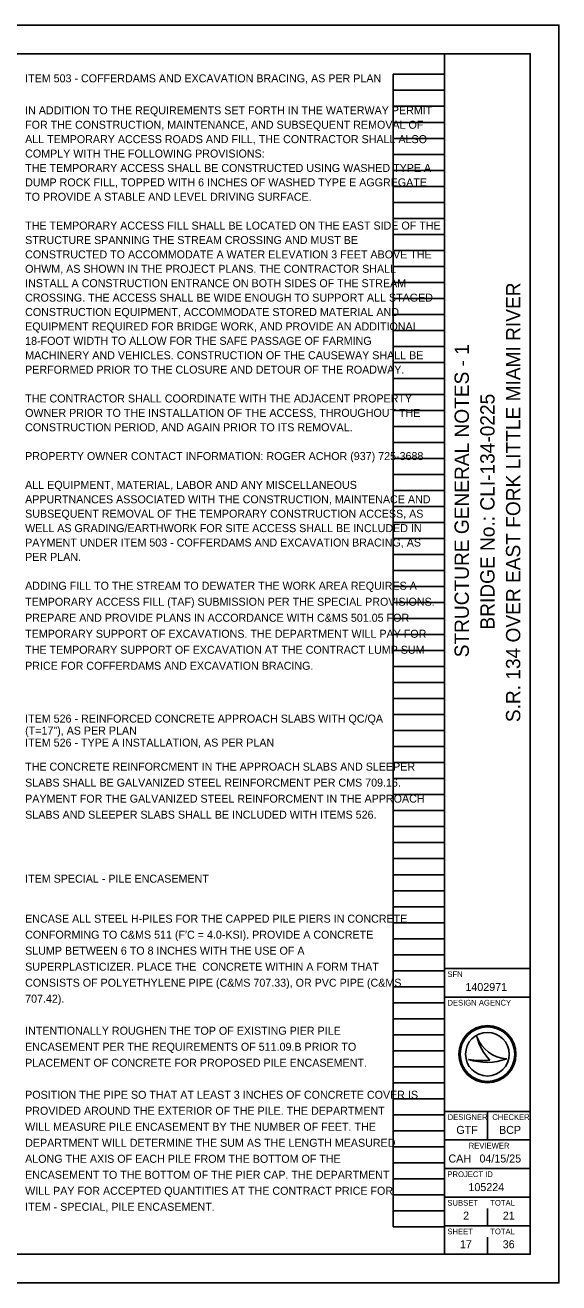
# Model space of a CAD drawing. Extents: x 0 to 48.4, y -19.4 to 22.
# Drawn here: x 24.66 to 34, y 0 to 22 of the extents above; entities that cross this region are included whole.
import ezdxf

# ---------------------------------------------------------------- set-up
doc = ezdxf.new("R2010")
doc.units = 0
for name, color, linetype in [('BR_P_Gen_Text', 7, 'Continuous'), ('SH_Border', 7, 'Continuous'), ('SH_Cut_Line', 7, 'Continuous'), ('SH_Data', 7, 'Continuous'), ('SH_Text', 7, 'Continuous')]:
    doc.layers.add(name, color=color, linetype=linetype)

msp = doc.modelspace()

# ---------------------------------------------------------------- linework, layer by layer
at = {"layer": 'SH_Border'}
for p, q in [((32, 0.5), (32, 21.5)), ((32, 5.5), (33.5, 5.5)), ((32, 5), (33.5, 5)), ((32, 3), (33.5, 3)), ((32.75, 3), (32.75, 2.5)), ((32, 2.5), (33.5, 2.5)), ((32, 2), (33.5, 2)), ((32, 1.5), (33.5, 1.5)), ((32, 1), (33.5, 1))]:
    msp.add_line(p, q, dxfattribs=at)
msp.add_lwpolyline([(1.5, 21.5), (33.5, 21.5), (33.5, 0.5), (1.5, 0.5)], close=True, dxfattribs=at)
at = {"layer": 'SH_Cut_Line'}
msp.add_lwpolyline([(0, 0), (34, 0), (34, 22), (0, 22)], close=True, dxfattribs=at)
at = {"layer": 'SH_Data'}
for p, q in [((31.1, 0.98), (31.1, 21.14)), ((31.1, 21.14), (32, 21.14)), ((32, 0.98), (32, 21.14)), ((31.1, 20.86), (32, 20.86)), ((31.1, 20.58), (32, 20.58)), ((31.1, 20.3), (32, 20.3)), ((31.1, 20.02), (32, 20.02)), ((31.1, 19.74), (32, 19.74)), ((31.1, 19.46), (32, 19.46)), ((31.1, 19.18), (32, 19.18)), ((31.1, 18.9), (32, 18.9)), ((31.1, 18.62), (32, 18.62)), ((31.1, 18.34), (32, 18.34)), ((31.1, 18.06), (32, 18.06)), ((31.1, 17.78), (32, 17.78)), ((31.1, 17.5), (32, 17.5)), ((31.1, 17.22), (32, 17.22)), ((31.1, 16.94), (32, 16.94)), ((31.1, 16.66), (32, 16.66)), ((31.1, 16.38), (32, 16.38)), ((31.1, 16.1), (32, 16.1)), ((31.1, 15.82), (32, 15.82)), ((31.1, 15.54), (32, 15.54)), ((31.1, 15.26), (32, 15.26)), ((31.1, 14.98), (32, 14.98)), ((31.1, 14.7), (32, 14.7)), ((31.1, 14.42), (32, 14.42)), ((31.1, 14.14), (32, 14.14)), ((31.1, 13.86), (32, 13.86)), ((31.1, 13.58), (32, 13.58)), ((31.1, 13.3), (32, 13.3)), ((31.1, 13.02), (32, 13.02)), ((31.1, 12.74), (32, 12.74)), ((31.1, 12.46), (32, 12.46)), ((31.1, 12.18), (32, 12.18)), ((31.1, 11.9), (32, 11.9)), ((31.1, 11.62), (32, 11.62)), ((31.1, 11.34), (32, 11.34)), ((31.1, 11.06), (32, 11.06)), ((31.1, 10.78), (32, 10.78)), ((31.1, 10.5), (32, 10.5)), ((31.1, 10.22), (32, 10.22)), ((31.1, 9.94), (32, 9.94)), ((31.1, 9.66), (32, 9.66)), ((31.1, 9.38), (32, 9.38)), ((31.1, 9.1), (32, 9.1)), ((31.1, 8.82), (32, 8.82)), ((31.1, 8.54), (32, 8.54)), ((31.1, 8.26), (32, 8.26)), ((31.1, 7.98), (32, 7.98)), ((31.1, 7.7), (32, 7.7)), ((31.1, 7.42), (32, 7.42)), ((31.1, 7.14), (32, 7.14)), ((31.1, 6.86), (32, 6.86)), ((31.1, 6.58), (32, 6.58)), ((31.1, 6.3), (32, 6.3)), ((31.1, 6.02), (32, 6.02)), ((31.1, 5.74), (32, 5.74)), ((31.1, 5.46), (32, 5.46)), ((31.1, 5.18), (32, 5.18)), ((31.1, 4.9), (32, 4.9)), ((31.1, 4.62), (32, 4.62)), ((31.1, 4.34), (32, 4.34)), ((32.567, 4.31), (32.567, 4.31)), ((31.1, 4.06), (32, 4.06)), ((32.75, 4), (32.75, 4)), ((31.1, 3.78), (32, 3.78)), ((32.417, 3.91), (32.417, 3.91)), ((33.087, 3.919), (33.087, 3.919)), ((31.1, 3.5), (32, 3.5)), ((31.1, 3.22), (32, 3.22)), ((31.1, 2.94), (32, 2.94)), ((31.1, 2.66), (32, 2.66)), ((31.1, 2.38), (32, 2.38)), ((31.1, 2.1), (32, 2.1)), ((31.1, 1.82), (32, 1.82)), ((31.1, 1.54), (32, 1.54)), ((31.1, 1.26), (32, 1.26)), ((32.75, 1), (32.75, 1.3)), ((31.1, 0.98), (32, 0.98)), ((32.375, 0.675), (32.375, 0.675)), ((32.75, 0.5), (32.75, 0.8))]:
    msp.add_line(p, q, dxfattribs=at)
for radius in [0.5, 0.477, 0.477, 0.382]:
    msp.add_circle((32.75, 4), radius, dxfattribs=at)
for centre, radius, start, end in [((33.116, 4.498), 0.58, 198.9257, 198.9319), ((33.347, 4.47), 0.796, 191.6379, 191.6421), ((33.116, 4.498), 0.58, 198.9319, 267.1657), ((33.347, 4.47), 0.796, 191.6421, 226.0947), ((32.739, 4.87), 1.013, 251.4576, 290.0832), ((32.648, 5.154), 1.266, 259.4964, 259.4995), ((32.739, 4.87), 1.013, 251.4527, 251.4576), ((32.648, 5.154), 1.266, 259.4995, 276.6672)]:
    msp.add_arc(centre, radius, start, end, dxfattribs=at)

# ---------------------------------------------------------------- texts
at = {"layer": 'BR_P_Gen_Text'}
for s, p in [('ITEM 526 - REINFORCED CONCRETE APPROACH SLABS WITH QC/QA ', (24.66, 9.8)), ('(T=17"), AS PER PLAN', (24.66, 9.59)), ('ITEM 526 - TYPE A INSTALLATION, AS PER PLAN', (24.66, 9.38)), ('THE CONCRETE REINFORCMENT IN THE APPROACH SLABS AND SLEEPER ', (24.66, 8.96)), ('SLABS SHALL BE GALVANIZED STEEL REINFORCMENT PER CMS 709.16. ', (24.66, 8.68)), ('PAYMENT FOR THE GALVANIZED STEEL REINFORCMENT IN THE APPROACH ', (24.66, 8.4)), ('SLABS AND SLEEPER SLABS SHALL BE INCLUDED WITH ITEMS 526.', (24.66, 8.12))]:
    msp.add_text(s, height=0.14, dxfattribs=at).set_placement(p)
at = {"layer": 'SH_Data'}
for s, p in [('S.R. 134 OVER EAST FORK LITTLE MIAMI RIVER', (33.325, 9.808)), ('STRUCTURE GENERAL NOTES - 1', (32.425, 10.942)), ('BRIDGE No.: CLI-134-0225', (32.875, 11.427))]:
    msp.add_text(s, height=0.25, rotation=90, dxfattribs=at).set_placement(p)
for s, height, p in [('SFN', 0.1, (32.05, 5.35)), ('1402971', 0.14, (32.365, 5.105)), ('DESIGN AGENCY', 0.1, (32.05, 4.85)), ('DESIGNER', 0.1, (32.054, 2.85)), ('CHECKER', 0.1, (32.835, 2.85)), ('GTF', 0.14, (32.206, 2.605)), ('BCP', 0.14, (32.954, 2.605)), ('REVIEWER', 0.1, (32.422, 2.35)), ('CAH', 0.14, (32.068, 2.105)), ('04/15/25', 0.14, (32.611, 2.105)), ('PROJECT ID', 0.1, (32.05, 1.85)), ('105224', 0.14, (32.418, 1.605)), ('SUBSET', 0.1, (32.05, 1.35)), ('TOTAL', 0.1, (32.8, 1.35)), ('2', 0.14, (32.325, 1.105)), ('21', 0.14, (33.019, 1.105)), ('SHEET', 0.1, (32.05, 0.85)), ('TOTAL', 0.1, (32.8, 0.85)), ('17', 0.14, (32.268, 0.605)), ('36', 0.14, (33.018, 0.605))]:
    msp.add_text(s, height=height, dxfattribs=at).set_placement(p)
at = {"layer": 'SH_Text'}
for s, p in [('ITEM 503 - COFFERDAMS AND EXCAVATION BRACING, AS PER PLAN', (24.66, 21)), ('IN ADDITION TO THE REQUIREMENTS SET FORTH IN THE WATERWAY PERMIT ', (24.66, 20.44)), ('FOR THE CONSTRUCTION, MAINTENANCE, AND SUBSEQUENT REMOVAL OF ', (24.66, 20.188)), ('ALL TEMPORARY ACCESS ROADS AND FILL, THE CONTRACTOR SHALL ALSO ', (24.66, 19.936)), ('COMPLY WITH THE FOLLOWING PROVISIONS:', (24.66, 19.684)), ('THE TEMPORARY ACCESS SHALL BE CONSTRUCTED USING WASHED TYPE A ', (24.66, 19.432)), ('DUMP ROCK FILL, TOPPED WITH 6 INCHES OF WASHED TYPE E AGGREGATE ', (24.66, 19.18)), ('TO PROVIDE A STABLE AND LEVEL DRIVING SURFACE. ', (24.66, 18.928)), ('THE TEMPORARY ACCESS FILL SHALL BE LOCATED ON THE EAST SIDE OF THE ', (24.66, 18.424)), ('STRUCTURE SPANNING THE STREAM CROSSING AND MUST BE ', (24.66, 18.172)), ('CONSTRUCTED TO ACCOMMODATE A WATER ELEVATION 3 FEET ABOVE THE ', (24.66, 17.92)), ('OHWM, AS SHOWN IN THE PROJECT PLANS. THE CONTRACTOR SHALL ', (24.66, 17.668)), ('INSTALL A CONSTRUCTION ENTRANCE ON BOTH SIDES OF THE STREAM ', (24.66, 17.416)), ('CROSSING. THE ACCESS SHALL BE WIDE ENOUGH TO SUPPORT ALL STAGED ', (24.66, 17.164)), ('CONSTRUCTION EQUIPMENT, ACCOMMODATE STORED MATERIAL AND ', (24.66, 16.912)), ('EQUIPMENT REQUIRED FOR BRIDGE WORK, AND PROVIDE AN ADDITIONAL ', (24.66, 16.66)), ('18-FOOT WIDTH TO ALLOW FOR THE SAFE PASSAGE OF FARMING ', (24.66, 16.408)), ('MACHINERY AND VEHICLES. CONSTRUCTION OF THE CAUSEWAY SHALL BE ', (24.66, 16.156)), ('PERFORMED PRIOR TO THE CLOSURE AND DETOUR OF THE ROADWAY.', (24.66, 15.904)), ('THE CONTRACTOR SHALL COORDINATE WITH THE ADJACENT PROPERTY ', (24.66, 15.4)), ('OWNER PRIOR TO THE INSTALLATION OF THE ACCESS, THROUGHOUT THE ', (24.66, 15.148)), ('CONSTRUCTION PERIOD, AND AGAIN PRIOR TO ITS REMOVAL.', (24.66, 14.896)), ('PROPERTY OWNER CONTACT INFORMATION: ROGER ACHOR (937) 725-3688', (24.66, 14.392)), ('ALL EQUIPMENT, MATERIAL, LABOR AND ANY MISCELLANEOUS ', (24.66, 13.888)), ('APPURTNANCES ASSOCIATED WITH THE CONSTRUCTION, MAINTENACE AND ', (24.66, 13.636)), ('SUBSEQUENT REMOVAL OF THE TEMPORARY CONSTRUCTION ACCESS, AS ', (24.66, 13.384)), ('WELL AS GRADING/EARTHWORK FOR SITE ACCESS SHALL BE INCLUDED IN ', (24.66, 13.132)), ('PAYMENT UNDER ITEM 503 - COFFERDAMS AND EXCAVATION BRACING, AS ', (24.66, 12.88)), ('PER PLAN.', (24.66, 12.628)), ('ADDING FILL TO THE STREAM TO DEWATER THE WORK AREA REQUIRES A ', (24.66, 12.124)), ('TEMPORARY ACCESS FILL (TAF) SUBMISSION PER THE SPECIAL PROVISIONS.', (24.66, 11.844)), ('PREPARE AND PROVIDE PLANS IN ACCORDANCE WITH C&MS 501.05 FOR ', (24.66, 11.564)), ('TEMPORARY SUPPORT OF EXCAVATIONS. THE DEPARTMENT WILL PAY FOR ', (24.66, 11.284)), ('THE TEMPORARY SUPPORT OF EXCAVATION AT THE CONTRACT LUMP SUM ', (24.66, 11.004)), ('PRICE FOR COFFERDAMS AND EXCAVATION BRACING. ', (24.66, 10.724)), ('ITEM SPECIAL - PILE ENCASEMENT', (24.66, 7)), ('ENCASE ALL STEEL H-PILES FOR THE CAPPED PILE PIERS IN CONCRETE ', (24.66, 6.3)), ('CONFORMING TO C&MS 511 (F′C = 4.0-KSI). PROVIDE A CONCRETE ', (24.66, 6.02)), ('SLUMP BETWEEN 6 TO 8 INCHES WITH THE USE OF A ', (24.66, 5.74)), ('SUPERPLASTICIZER. PLACE THE  CONCRETE WITHIN A FORM THAT ', (24.66, 5.46)), ('CONSISTS OF POLYETHYLENE PIPE (C&MS 707.33), OR PVC PIPE (C&MS ', (24.66, 5.18)), ('707.42). ', (24.66, 4.9)), ('INTENTIONALLY ROUGHEN THE TOP OF EXISTING PIER PILE ', (24.66, 4.34)), ('ENCASEMENT PER THE REQUIREMENTS OF 511.09.B PRIOR TO ', (24.66, 4.06)), ('PLACEMENT OF CONCRETE FOR PROPOSED PILE ENCASEMENT.', (24.66, 3.78)), ('POSITION THE PIPE SO THAT AT LEAST 3 INCHES OF CONCRETE COVER IS ', (24.66, 3.22)), ('PROVIDED AROUND THE EXTERIOR OF THE PILE. THE DEPARTMENT ', (24.66, 2.94)), ('WILL MEASURE PILE ENCASEMENT BY THE NUMBER OF FEET. THE ', (24.66, 2.66)), ('DEPARTMENT WILL DETERMINE THE SUM AS THE LENGTH MEASURED ', (24.66, 2.38)), ('ALONG THE AXIS OF EACH PILE FROM THE BOTTOM OF THE ', (24.66, 2.1)), ('ENCASEMENT TO THE BOTTOM OF THE PIER CAP. THE DEPARTMENT ', (24.66, 1.82)), ('WILL PAY FOR ACCEPTED QUANTITIES AT THE CONTRACT PRICE FOR ', (24.66, 1.54)), ('ITEM - SPECIAL, PILE ENCASEMENT.', (24.66, 1.26))]:
    msp.add_text(s, height=0.14, dxfattribs=at).set_placement(p)

doc.saveas('drawing.dxf')
